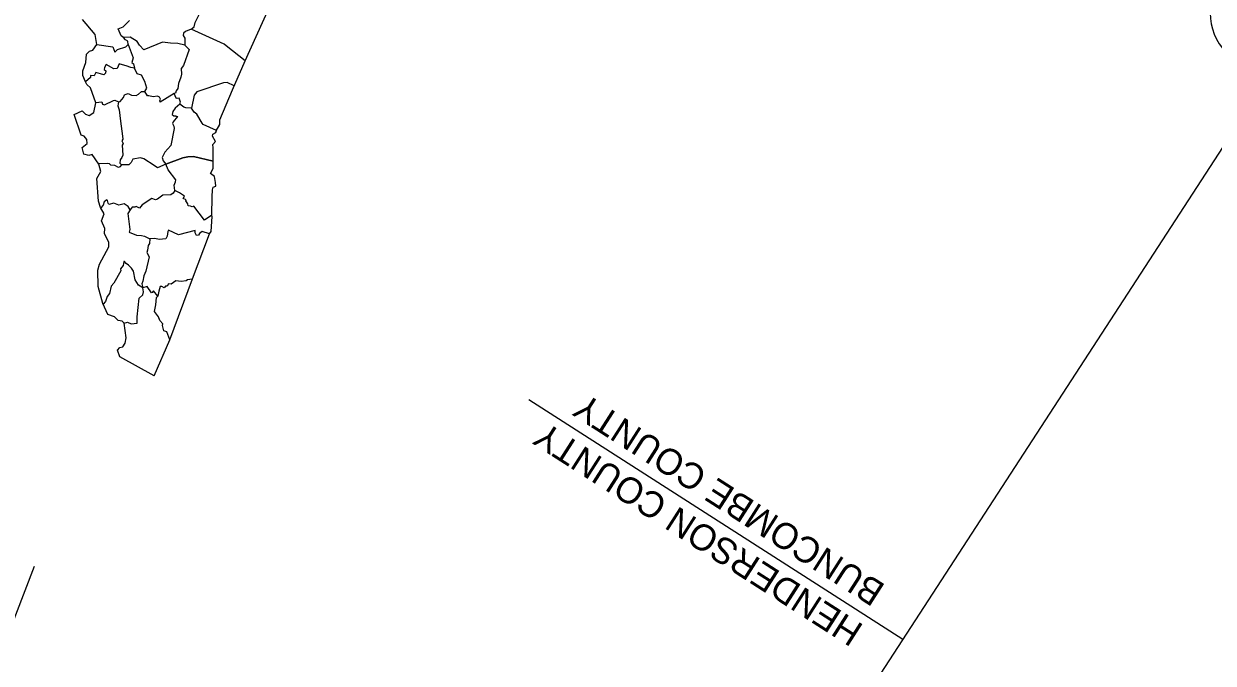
# Model space of a CAD drawing. Extents: x 1015221 to 1064345, y 619216 to 647967.
# Drawn here: x 1021098 to 1023380, y 644303 to 645531 of the extents above; entities that cross this region are included whole.
import ezdxf

# ---------------------------------------------------------------- set-up
doc = ezdxf.new("R2010")
doc.units = 0
for name, color, linetype in [('Default', 7, 'Continuous'), ('Old_Level_20', 7, 'Continuous'), ('Prop DSN Text', 7, 'Continuous'), ('Scratch_Level_2', 7, 'Continuous'), ('Sheet North Arrow CELL', 7, 'Continuous')]:
    doc.layers.add(name, color=color, linetype=linetype)

msp = doc.modelspace()

# ---------------------------------------------------------------- linework, layer by layer
at = {"layer": 'Default'}
msp.add_line((1022784.7, 644349.3), (1022067.3, 644809.2), dxfattribs=at)
at = {"layer": 'Old_Level_20'}
for points in [[(1021348.6, 644855), (1021378.3, 644924.1), (1021421.7, 645041.1), (1021454.4, 645127.4), (1021457.9, 645132.1), (1021460, 645160.6), (1021459.1, 645163.6), (1021459.5, 645198.4), (1021460.2, 645212.1), (1021461.5, 645216.9), (1021466.5, 645219.2), (1021466.2, 645226.2), (1021464.4, 645237.5), (1021456.4, 645243.1), (1021461.9, 645253.1), (1021461.5, 645268.5), (1021461.8, 645292.6), (1021460.7, 645299.3), (1021466.2, 645304.5), (1021460.4, 645314.9), (1021461.2, 645318.6), (1021466.4, 645322.2), (1021467.5, 645325.1), (1021474.2, 645337.1), (1021474.5, 645346.6), (1021498.8, 645403.7), (1021523.1, 645459.4), (1021568.6, 645559.7)], [(1021348.6, 644855), (1021282.3, 644891.4), (1021278.2, 644904.5), (1021282.4, 644909.3), (1021288.2, 644910.8), (1021292.5, 644917.5), (1021295, 644927.8), (1021290.6, 644956.4), (1021290.6, 644956.4), (1021286.7, 644960.1), (1021279.5, 644960.9), (1021272.5, 644968.1), (1021259.2, 644972.9), (1021250.1, 644994), (1021240.7, 645026.3), (1021240.2, 645057.8), (1021243.3, 645069), (1021261.5, 645102.5), (1021261.4, 645111), (1021253, 645128.2), (1021254, 645137.6), (1021247.5, 645152.7), (1021252.2, 645165.6), (1021245.5, 645178.1), (1021241.4, 645190), (1021238.6, 645233.6), (1021245.8, 645247.2), (1021242.5, 645261.5), (1021229.3, 645280.1), (1021223.2, 645277.6), (1021213.6, 645280.6), (1021210.5, 645293), (1021220, 645301.2), (1021219, 645308.8), (1021213.8, 645314.9), (1021208.1, 645317.2), (1021194.7, 645356.6), (1021210.5, 645363.7), (1021216.8, 645357.2), (1021223.9, 645354.8), (1021232.4, 645360.4), (1021236.7, 645379.2), (1021226.1, 645407.6), (1021219.4, 645414.3), (1021216.5, 645419.4), (1021211.8, 645431.1), (1021211.5, 645440.6), (1021217.4, 645456.6), (1021218.3, 645472.3), (1021224.2, 645478), (1021230.9, 645480.3), (1021238.2, 645490.8), (1021235.2, 645510.3), (1021210.9, 645539.1)], [(1021289.4, 645504.6), (1021284.9, 645507.6), (1021279.6, 645521.1), (1021288.9, 645524.9), (1021292.4, 645527.7), (1021301.1, 645536.7)], [(1021419.5, 645520.1), (1021425.3, 645524.7), (1021427.1, 645533.4), (1021431.3, 645541.9), (1021434.4, 645547.1), (1021436.2, 645555.4)], [(1021419.5, 645520.1), (1021408.7, 645515.6), (1021405, 645512.5), (1021403.9, 645508), (1021407.1, 645503.3), (1021407.5, 645489.6)], [(1021523.1, 645459.4), (1021486.4, 645488.1), (1021482.7, 645491.8), (1021419.5, 645520.1)], [(1021298.8, 645490.8), (1021308.3, 645465.4), (1021305.6, 645456.6), (1021308.7, 645453.6), (1021310.8, 645445.6), (1021303.7, 645446.9), (1021294.9, 645450), (1021287.6, 645451.7), (1021281.5, 645454.1), (1021277.7, 645444.6), (1021271.1, 645444), (1021256.3, 645452.5), (1021252.9, 645446.5), (1021252.4, 645442.8), (1021255.7, 645440.5), (1021255, 645435.7), (1021252.1, 645432.6), (1021245.5, 645434.8), (1021236.8, 645436.9), (1021233.1, 645431), (1021226.3, 645431.3), (1021226.2, 645427.8), (1021216.5, 645419.5)], [(1021238.2, 645490.9), (1021269.1, 645486.7), (1021272.7, 645475.9), (1021278.1, 645481.2), (1021294.2, 645486.7), (1021298.8, 645490.8)], [(1021407.5, 645489.6), (1021393.8, 645493.1), (1021380, 645493.5), (1021364.1, 645495.1), (1021328.6, 645480.4), (1021320.2, 645489.7), (1021315.6, 645496.7), (1021302.3, 645505.2), (1021289.4, 645504.6)], [(1021298.8, 645490.8), (1021298, 645497.6), (1021293.3, 645499.6), (1021289.4, 645504.6)], [(1021407.5, 645489.6), (1021415.7, 645481.3), (1021404.8, 645450.6), (1021400, 645445), (1021400.9, 645434.2), (1021399.8, 645428.1), (1021395.4, 645416.3), (1021393.6, 645406.2), (1021390.9, 645402.2), (1021389.5, 645397.7), (1021386.6, 645396.7)], [(1021323.9, 645432.2), (1021315.7, 645434.9), (1021310.8, 645445.6)], [(1021330.3, 645400.7), (1021334.5, 645407.4), (1021330.4, 645420.1), (1021323.9, 645432.2)], [(1021280.3, 645380.6), (1021283.1, 645381.4), (1021289.6, 645388.9), (1021291.8, 645394), (1021294.8, 645395.9), (1021298.5, 645396.9), (1021305.2, 645393.5), (1021314, 645393.3), (1021318.6, 645395.8), (1021323.8, 645400.8), (1021330.3, 645400.7)], [(1021386.6, 645396.7), (1021359.8, 645380.3), (1021359.3, 645382.9), (1021360.4, 645386.3), (1021358.7, 645390), (1021354.5, 645391.6), (1021346.5, 645390.6), (1021338.2, 645392.6), (1021335.5, 645392.5), (1021330.3, 645400.7)], [(1021502.1, 645411.3), (1021488.7, 645417.8), (1021481.4, 645417.3), (1021430.2, 645399.9), (1021425.4, 645393.5), (1021420.1, 645368.4)], [(1021236.7, 645379.3), (1021247.9, 645380.8), (1021249.5, 645376.7), (1021253.4, 645375.2), (1021270.2, 645383.6), (1021272.8, 645384.1), (1021280.3, 645380.6)], [(1021280.3, 645380.6), (1021278.8, 645373.1), (1021281.1, 645365.5), (1021284, 645343.5), (1021287.5, 645315), (1021288.1, 645309.1), (1021286.1, 645306.2), (1021288.9, 645300.7), (1021287.2, 645297.7), (1021288.3, 645278.8), (1021286.4, 645274), (1021283.3, 645269.8), (1021282.3, 645263.2), (1021286, 645260)], [(1021397.5, 645376.6), (1021388.5, 645369), (1021384.3, 645362.3), (1021383.1, 645356.7), (1021386.1, 645353.8), (1021389.3, 645353.9), (1021393.1, 645353), (1021384.6, 645342.8), (1021383.5, 645339.4), (1021386.4, 645334.2), (1021386.8, 645330), (1021380.7, 645297.1), (1021369, 645284), (1021364, 645274.2), (1021365.9, 645267.9), (1021370.6, 645261)], [(1021397.5, 645376.6), (1021388.5, 645369), (1021384.3, 645362.3), (1021383.1, 645356.7), (1021386.1, 645353.8), (1021393.1, 645353), (1021384.6, 645342.8), (1021383.5, 645339.4), (1021386.4, 645334.2), (1021386.8, 645330), (1021380.7, 645297.1), (1021369, 645284), (1021364, 645274.2), (1021365.9, 645267.9), (1021370.6, 645261)], [(1021397.5, 645376.6), (1021398.9, 645380.5), (1021396.3, 645387.6), (1021392.6, 645387.3), (1021390.4, 645388.2), (1021386.6, 645396.7)], [(1021420.1, 645368.4), (1021408.9, 645369.3), (1021405.6, 645370.4), (1021397.5, 645376.6)], [(1021420.1, 645368.4), (1021408.9, 645369.3), (1021405.6, 645370.4), (1021397.5, 645376.6)], [(1021467.9, 645325.8), (1021442.7, 645337.4), (1021440.2, 645340), (1021430.1, 645357.2), (1021425.3, 645361.1), (1021420.1, 645368.4)], [(1021467.9, 645325.8), (1021442.7, 645337.4), (1021440.2, 645340), (1021430.1, 645357.2), (1021425.3, 645361.1), (1021420.1, 645368.4)], [(1021461.5, 645267.1), (1021461.8, 645292.6), (1021460.7, 645299.3), (1021466.2, 645304.5), (1021460.4, 645314.9), (1021461.2, 645318.6), (1021466.4, 645322.2), (1021467.9, 645325.8)], [(1021286, 645260), (1021282.6, 645256), (1021280.1, 645255), (1021272.8, 645258.7), (1021265.1, 645259.5), (1021262.4, 645261.7), (1021259.7, 645262.5), (1021242.2, 645261.9)], [(1021370.6, 645261), (1021354.8, 645254.4), (1021348.5, 645258.4), (1021328.7, 645271.6), (1021321.9, 645273.4), (1021307.3, 645270.9), (1021304.5, 645264.6), (1021299.9, 645259.7), (1021286, 645260)], [(1021461.5, 645267.1), (1021423.6, 645276), (1021413.3, 645275.5), (1021403.1, 645273.4), (1021370.6, 645261)], [(1021370.6, 645261), (1021403.1, 645273.4), (1021413.3, 645275.5), (1021423.6, 645276), (1021461.5, 645267.1)], [(1021388.3, 645210.8), (1021386.8, 645220.7), (1021389.5, 645227.5), (1021389.7, 645231.3), (1021375, 645250.2), (1021370.6, 645261)], [(1021388.3, 645210.8), (1021385, 645205.5), (1021380.1, 645202.4), (1021364.9, 645201.5), (1021354.5, 645193.9), (1021350.8, 645192.8), (1021343.9, 645195.1), (1021325.4, 645183.4), (1021320, 645176.5), (1021314.1, 645179.8), (1021311.5, 645178.6), (1021306.4, 645178.6), (1021302.5, 645173.7)], [(1021459.1, 645163.6), (1021445.1, 645153.7), (1021424.8, 645180.4), (1021421.4, 645179.2), (1021418.3, 645180.6), (1021413.6, 645181.2), (1021413.3, 645185.4), (1021409.3, 645190.7), (1021409.5, 645192.6), (1021403.8, 645195.4), (1021406.3, 645199.9), (1021397.3, 645206.1), (1021388.3, 645210.8)], [(1021302.5, 645173.7), (1021298.7, 645180.1), (1021290.9, 645184.9), (1021280.5, 645182.8), (1021270.9, 645186.6), (1021261.4, 645183.6), (1021260.2, 645186.2), (1021258.9, 645191.7), (1021257.6, 645192.8), (1021252.7, 645188.8), (1021250.7, 645182.4), (1021245.8, 645177.3)], [(1021302.5, 645173.7), (1021297.8, 645166.5), (1021301.6, 645135.6), (1021300.2, 645130.8), (1021314.4, 645124.9), (1021324.4, 645124.1), (1021329.9, 645123), (1021340.2, 645117.7)], [(1021454.4, 645127.4), (1021440.3, 645131.8), (1021435.1, 645128), (1021433.3, 645124.7), (1021429.9, 645124.2), (1021427.2, 645129.7), (1021426.8, 645133.8), (1021395.3, 645125.9), (1021376.2, 645134.6), (1021374.6, 645132.3), (1021373.2, 645122.9), (1021371, 645118.2), (1021357.9, 645116.9), (1021349.8, 645118.3), (1021340.2, 645117.7)], [(1021340.2, 645117.7), (1021339.3, 645109.1), (1021337.2, 645105.2), (1021335.7, 645096.2), (1021334.1, 645092), (1021338.6, 645083.2), (1021332.3, 645055.7), (1021328.5, 645047.2), (1021326.4, 645037), (1021324.7, 645031.3), (1021326.6, 645024)], [(1021326.6, 645024), (1021318.4, 645028.9), (1021311.7, 645039.2), (1021308.5, 645055.9), (1021305, 645061.4), (1021299.2, 645067.7), (1021294.4, 645070.4), (1021291.3, 645074.5), (1021290.3, 645074.2), (1021289.2, 645066.5), (1021283.9, 645060.4), (1021284.4, 645056.3), (1021270.9, 645033), (1021266.1, 645027), (1021262.6, 645012.9), (1021258.4, 645007.3), (1021256.1, 645001.5), (1021255, 644997.4), (1021250.6, 644992.5)], [(1021421.5, 645040.5), (1021412.1, 645039.4), (1021409.9, 645037.5), (1021400.3, 645036.2), (1021390.2, 645037.4), (1021381.1, 645030.7), (1021375.9, 645031.7), (1021373.1, 645027.3), (1021370.2, 645027), (1021367.3, 645023.8), (1021363.1, 645026.6), (1021360.2, 645026.2), (1021357.1, 645017.8), (1021355.3, 645008.2)], [(1021290.6, 644956.4), (1021297.3, 644958.2), (1021304.3, 644954.8), (1021315.9, 644956.3), (1021315.7, 644968.1), (1021319.7, 645004.3), (1021326.7, 645010.2), (1021327.7, 645016.3), (1021326.6, 645024)], [(1021355.3, 645008.2), (1021347.2, 645018.1), (1021344.8, 645015.1), (1021343.1, 645014.1), (1021334.9, 645026.5), (1021326.6, 645024)], [(1021378.3, 644924.1), (1021372.4, 644939.4), (1021366.9, 644941.3), (1021364.7, 644951.4), (1021364.9, 644954.5), (1021359.1, 644961.5), (1021357, 644968.2), (1021349.3, 644978.2), (1021351.9, 644991.3), (1021352.6, 645005.4), (1021355.3, 645008.2)]]:
    msp.add_lwpolyline(points, dxfattribs=at)
at = {"layer": 'Prop DSN Text'}
msp.add_lwpolyline([(1023225.6, 640401.1), (1020495.1, 642865.6), (1021119.1, 644489.5)], dxfattribs=at)
at = {"layer": 'Scratch_Level_2'}
msp.add_lwpolyline([(1020895.4, 635853.8), (1022473.8, 638805.7), (1023379.2, 639473.6), (1023843, 640900.1), (1023637.3, 641036.3), (1023148.3, 642068.8), (1023188.2, 643043.1), (1024411.5, 644926.1), (1023531, 645498.1), (1022160.6, 643388.7), (1022151.2, 643382.8), (1022046.3, 641942.6), (1021939, 640556.9), (1021513.5, 639679.1), (1020439.2, 638632.2), (1020121.4, 637513.2), (1020059.5, 637223.8), (1019861.3, 636035.8)], close=True, dxfattribs=at)
at = {"layer": 'Sheet North Arrow CELL'}
msp.add_arc((1023483.4, 645551.5), 109.2, 47.84, 312.3941, dxfattribs=at)

# ---------------------------------------------------------------- texts
at = {"layer": 'Default'}
for s, p in [('BUNCOMBE COUNTY', (1022753.5, 644452.6)), ('HENDERSON COUNTY', (1022711.8, 644375.6))]:
    msp.add_text(s, height=50, rotation=147.3427, dxfattribs=at).set_placement(p)
at = {"layer": 'Prop DSN Text'}
msp.add_text('ROADWAY FINAL PLAN SET', height=100, rotation=68.983, dxfattribs=at).set_placement((1020819.5, 645290.4))

doc.saveas('drawing.dxf')
